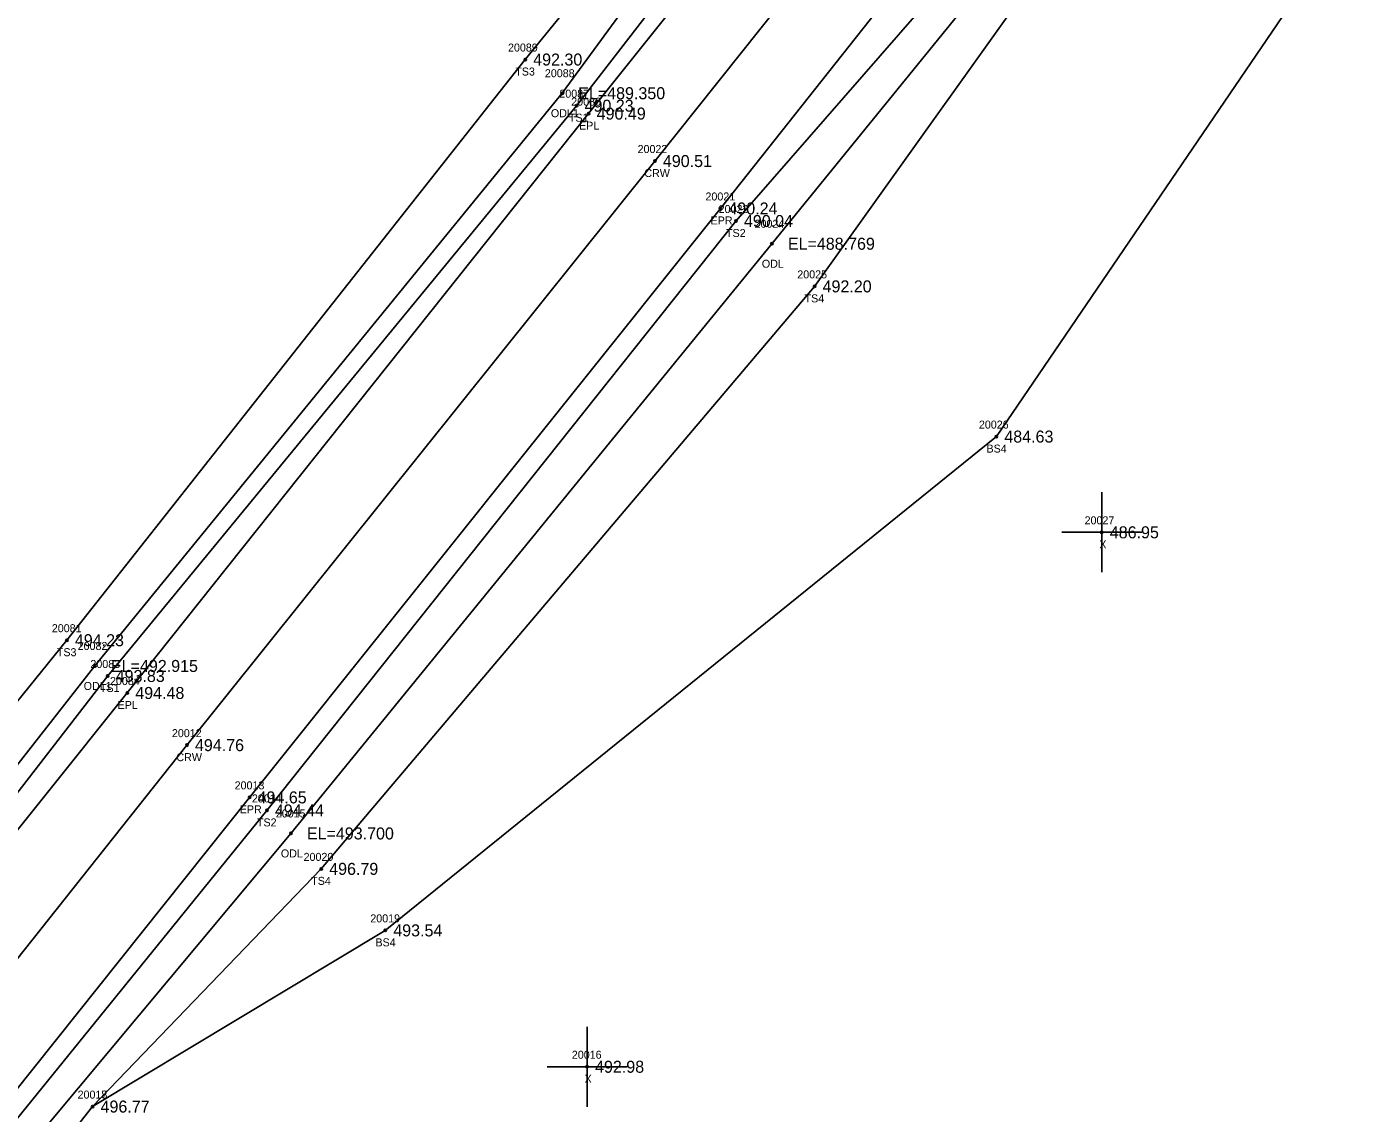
# Model space of a CAD drawing. Extents: x 1789565 to 1790548, y 909019 to 910194.
# Drawn here: x 1789725 to 1789890.1, y 909171.3 to 909307.2 of the extents above; entities that cross this region are included whole.
import ezdxf

# ---------------------------------------------------------------- set-up
doc = ezdxf.new("R2010")
doc.units = 0
for name, color, linetype in [('RD_DTM_BkLn1', 7, 'Continuous'), ('RD_DTM_BkLn2', 7, 'Continuous'), ('RD_DTM_BkLn_txCode', 7, 'Continuous'), ('RD_EX_H2O', 7, 'Continuous'), ('RD_EX_H2O_txCode', 7, 'Continuous'), ('RD_EX_Misc', 7, 'Continuous'), ('RD_EX_Misc_txCode', 7, 'Continuous'), ('RD_EX_Road', 7, 'Continuous'), ('RD_EX_Road_txCode', 7, 'Continuous'), ('RD_EX_TX_H2O_ELEV', 7, 'Continuous'), ('RD_EX_TX_Misc_ELEV', 7, 'Continuous'), ('RD_EX_TX_Road_ELEV', 7, 'Continuous'), ('RD_HC_Survey_ELEV', 7, 'Continuous'), ('RD_HC_Survey_txCode', 7, 'Continuous'), ('RD_SMD_Locator', 7, 'Continuous')]:
    doc.layers.add(name, color=color, linetype=linetype)

msp = doc.modelspace()

# ---------------------------------------------------------------- linework, layer by layer
at = {"layer": 'RD_DTM_BkLn1'}
msp.add_lwpolyline([(1789624.5, 909066.24), (1789686.15, 909143.09), (1789745.11, 909217.37), (1789803.6, 909290.4), (1789864.63, 909366.97), (1789927.82, 909445.41), (1789987.57, 909520.69), (1790044.94, 909592.68)], dxfattribs=at)
at = {"layer": 'RD_DTM_BkLn2'}
for points in [[(1789614.08, 909073.14), (1789676.68, 909150.35), (1789735.2, 909226.02), (1789793.81, 909297.32), (1789853.39, 909374.42), (1789917.15, 909454.46), (1789977.25, 909529.33), (1790025.37, 909589.9), (1790030.46, 909600.52), (1790034.43, 909600.71)], [(1789609.37, 909078.57), (1789669.9, 909156.07), (1789730.1, 909230.49), (1789787.39, 909303.09), (1789833.49, 909359.71), (1789838.38, 909362.25)], [(1789633.72, 909058.98), (1789695.06, 909135.14), (1789755.1, 909209.21), (1789813.73, 909282.9), (1789852.08, 909326.88), (1789859.67, 909329.95), (1789891.2, 909324.8)], [(1789638.21, 909054.4), (1789699.85, 909129.71), (1789733.31, 909172.18), (1789761.89, 909201.9), (1789823.56, 909274.73), (1789856.38, 909320.73), (1789862.75, 909322.59), (1789888.72, 909318.3)], [(1789733.31, 909172.18), (1789769.9, 909194.21), (1789846.28, 909255.95), (1789888.72, 909318.3)]]:
    msp.add_lwpolyline(points, dxfattribs=at)
at = {"layer": 'RD_EX_H2O'}
for points in [[(1789612.38, 909074.81), (1789674.47, 909151.77), (1789733.61, 909227.27), (1789792.01, 909298.88), (1789838.38, 909362.25)], [(1789635.36, 909056.96), (1789697.2, 909133.38), (1789758.1, 909206.33), (1789818.22, 909280.06), (1789854.18, 909324.3), (1789860.54, 909326.82), (1789889.88, 909320.33)]]:
    msp.add_lwpolyline(points, dxfattribs=at)
at = {"layer": 'RD_EX_Misc'}
for p, q in [((1789859.46, 909238.98), (1789859.46, 909248.98)), ((1789854.46, 909243.98), (1789864.46, 909243.98)), ((1789795.12, 909172.16), (1789795.12, 909182.16)), ((1789790.12, 909177.16), (1789800.12, 909177.16))]:
    msp.add_line(p, q, dxfattribs=at)
at = {"layer": 'RD_EX_Road'}
for points in [[(1789616.04, 909073.03), (1789678, 909149.36), (1789737.65, 909223.89), (1789795.32, 909296.33), (1789856.01, 909372.29), (1789919.82, 909451.94), (1789979.86, 909527.13), (1790037.32, 909598.58), (1790044.94, 909592.68)], [(1789632.25, 909060.17), (1789693.63, 909136.51), (1789752.94, 909210.84), (1789811.79, 909284.47), (1789846.6, 909328.43), (1789872.88, 909361.39), (1789936.05, 909439.58), (1789995.85, 909514.58), (1790052.72, 909586.51), (1790044.94, 909592.68)]]:
    msp.add_lwpolyline(points, dxfattribs=at)
at = {"layer": 'RD_SMD_Locator'}
for centre in [(1789787.39, 909303.09), (1789792.01, 909298.88), (1789793.81, 909297.32), (1789795.32, 909296.33), (1789803.6, 909290.4), (1789811.79, 909284.47), (1789813.73, 909282.9), (1789818.22, 909280.06), (1789823.56, 909274.73), (1789846.28, 909255.95), (1789859.46, 909243.98), (1789730.1, 909230.49), (1789733.61, 909227.27), (1789735.2, 909226.02), (1789737.65, 909223.89), (1789745.11, 909217.37), (1789752.94, 909210.84), (1789755.1, 909209.21), (1789758.1, 909206.33), (1789761.89, 909201.9), (1789769.9, 909194.21), (1789795.12, 909177.16), (1789733.31, 909172.18), (1789733.31, 909172.18)]:
    msp.add_circle(centre, 0.15, dxfattribs=at)

# ---------------------------------------------------------------- texts
at = {"layer": 'RD_DTM_BkLn_txCode'}
for s, p in [('20089', (1789785.24, 909304.09)), ('TS3', (1789786.15, 909301.09)), ('20087', (1789791.66, 909298.32)), ('TS1', (1789792.85, 909295.32)), ('20023', (1789811.57, 909283.9)), ('TS2', (1789812.49, 909280.9)), ('20025', (1789821.4, 909275.73)), ('TS4', (1789822.31, 909272.73)), ('20026', (1789844.1, 909256.95)), ('BS4', (1789845.05, 909253.95)), ('20081', (1789728.22, 909231.49)), ('TS3', (1789728.85, 909228.49)), ('20083', (1789733.04, 909227.02)), ('TS1', (1789734.24, 909224.02)), ('20014', (1789753.23, 909210.21)), ('TS2', (1789753.86, 909207.21)), ('20020', (1789759.69, 909202.9)), ('TS4', (1789760.64, 909199.9)), ('20019', (1789768.03, 909195.21)), ('BS4', (1789768.67, 909192.21)), ('20017', (1789731.44, 909173.18)), ('20018', (1789731.44, 909173.18))]:
    msp.add_text(s, height=1, dxfattribs=at).set_placement(p)
at = {"layer": 'RD_EX_H2O_txCode'}
for s, p in [('20088', (1789789.85, 909300.88)), ('ODL1', (1789790.6, 909295.88)), ('20024', (1789816.06, 909282.06)), ('ODL', (1789816.97, 909277.06)), ('20082', (1789731.45, 909229.27)), ('ODL1', (1789732.2, 909224.27)), ('20015', (1789756.22, 909208.33)), ('ODL', (1789756.85, 909203.33))]:
    msp.add_text(s, height=1, dxfattribs=at).set_placement(p)
at = {"layer": 'RD_EX_Misc_txCode'}
for s, p in [('20027', (1789857.31, 909244.98)), ('X', (1789859.15, 909241.98)), ('20016', (1789793.22, 909178.16)), ('X', (1789794.81, 909175.16))]:
    msp.add_text(s, height=1, dxfattribs=at).set_placement(p)
at = {"layer": 'RD_EX_Road_txCode'}
for s, p in [('20086', (1789793.14, 909297.33)), ('EPL', (1789794.12, 909294.33)), ('20021', (1789809.92, 909285.47)), ('EPR', (1789810.56, 909282.47)), ('20084', (1789735.49, 909224.89)), ('EPL', (1789736.44, 909221.89)), ('20013', (1789751.07, 909211.84)), ('EPR', (1789751.71, 909208.84))]:
    msp.add_text(s, height=1, dxfattribs=at).set_placement(p)
at = {"layer": 'RD_EX_TX_H2O_ELEV'}
for s, p in [('EL=489.350', (1789794.01, 909298.13)), ('EL=488.769', (1789820.22, 909279.31)), ('EL=492.915', (1789735.61, 909226.52)), ('EL=493.700', (1789760.1, 909205.58))]:
    msp.add_text(s, height=1.5, dxfattribs=at).set_placement(p)
at = {"layer": 'RD_EX_TX_Misc_ELEV'}
for s, p in [('492.30', (1789788.39, 909302.34)), ('490.23', (1789794.81, 909296.57)), ('490.04', (1789814.73, 909282.15)), ('492.20', (1789824.56, 909273.98)), ('484.63', (1789847.28, 909255.2)), ('486.95', (1789860.46, 909243.23)), ('494.23', (1789731.1, 909229.74)), ('493.83', (1789736.2, 909225.27)), ('494.44', (1789756.1, 909208.46)), ('496.79', (1789762.89, 909201.15)), ('493.54', (1789770.9, 909193.46)), ('492.98', (1789796.12, 909176.41)), ('496.77', (1789734.31, 909171.43)), ('496.77', (1789734.31, 909171.43))]:
    msp.add_text(s, height=1.5, dxfattribs=at).set_placement(p)
at = {"layer": 'RD_EX_TX_Road_ELEV'}
for s, p in [('490.49', (1789796.32, 909295.58)), ('490.24', (1789812.79, 909283.72)), ('494.48', (1789738.65, 909223.14)), ('494.65', (1789753.94, 909210.09))]:
    msp.add_text(s, height=1.5, dxfattribs=at).set_placement(p)
at = {"layer": 'RD_HC_Survey_ELEV'}
for s, p in [('490.51', (1789804.6, 909289.65)), ('494.76', (1789746.11, 909216.62))]:
    msp.add_text(s, height=1.5, dxfattribs=at).set_placement(p)
at = {"layer": 'RD_HC_Survey_txCode'}
for s, p in [('20022', (1789801.44, 909291.4)), ('CRW', (1789802.28, 909288.4)), ('20012', (1789743.23, 909218.37)), ('CRW', (1789743.79, 909215.37))]:
    msp.add_text(s, height=1, dxfattribs=at).set_placement(p)

doc.saveas('drawing.dxf')
